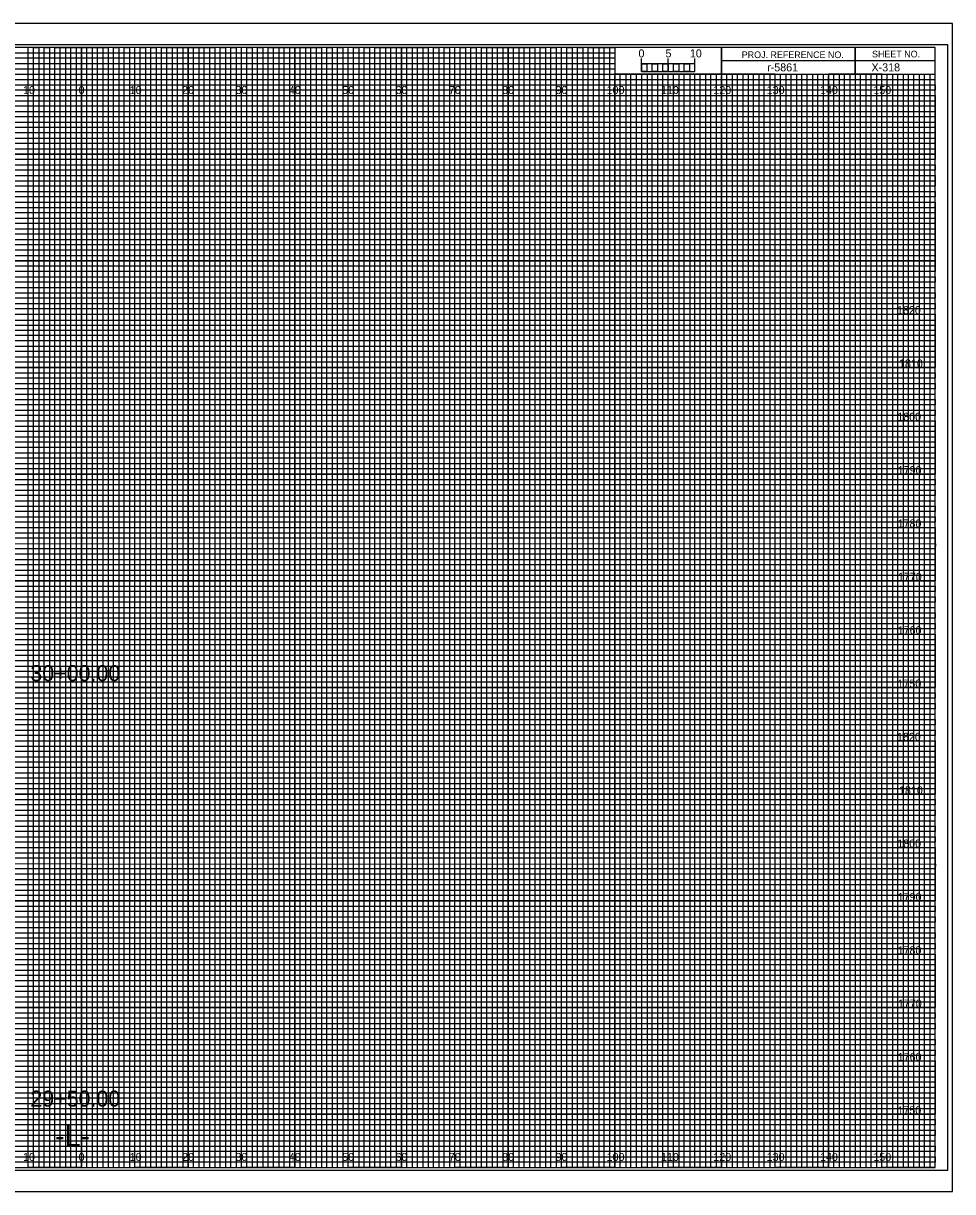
# Model space of a CAD drawing. Extents: x -15 to 323, y -5 to 6170.
# Drawn here: x 149.1 to 323.3, y 3075.5 to 3294.5 of the extents above; entities that cross this region are included whole.
import ezdxf

# ---------------------------------------------------------------- set-up
doc = ezdxf.new("R2010")
doc.units = 0
for name, color, linetype in [('Prop XS Alignment Label', 7, 'Continuous'), ('Prop XS Bar Scale Labels', 7, 'Continuous'), ('Prop XS DDE', 7, 'Continuous'), ('Prop XS DDE Earthwork Shape', 7, 'Continuous'), ('Prop XS DDE Slope Text', 7, 'Continuous'), ('Prop XS DDE Text', 7, 'Continuous'), ('Prop XS Earthwork Shape', 7, 'Continuous'), ('Prop XS Noise Wall', 7, 'Continuous'), ('Prop XS Project Number', 7, 'Continuous'), ('Prop XS Retaining Wall', 7, 'Continuous'), ('Prop XS Station Labels', 7, 'Continuous'), ('Prop XS Temporary Shoring', 7, 'Continuous'), ('Scratch_Level_3', 7, 'Continuous'), ('Scratch_Level_7', 7, 'Continuous'), ('Scratch_Level_8', 7, 'Continuous'), ('Sheet Cross Section Grid Minor 1 CELL', 7, 'Continuous')]:
    doc.layers.add(name, color=color, linetype=linetype)

msp = doc.modelspace()

# ---------------------------------------------------------------- linework, layer by layer
at = {"layer": 'Prop XS Alignment Label'}
for p, q in [((265, 3285.49), (265, 3287.9)), ((265, 3286.9), (265, 3287.9)), ((270, 3285.49), (270, 3287.9)), ((275, 3285.49), (275, 3287.9)), ((275, 3286.9), (275, 3287.9))]:
    msp.add_line(p, q, dxfattribs=at)
for points in [[(275, 3286.9), (265, 3286.9), (265, 3285.49), (275, 3285.49)], [(265, 3286.9), (266, 3286.9), (266, 3285.49), (265, 3285.49)], [(267, 3286.9), (268, 3286.9), (268, 3285.49), (267, 3285.49)], [(269, 3286.9), (270, 3286.9), (270, 3285.49), (269, 3285.49)], [(271, 3286.9), (272, 3286.9), (272, 3285.49), (271, 3285.49)], [(273, 3286.9), (274, 3286.9), (274, 3285.49), (273, 3285.49)]]:
    msp.add_lwpolyline(points, close=True, dxfattribs=at)
at = {"layer": 'Prop XS DDE'}
msp.add_lwpolyline([(-13.4, 3075.5), (323.3, 3075.5), (323.3, 3294.5), (-13.4, 3294.5)], close=True, dxfattribs=at)
at = {"layer": 'Prop XS DDE Slope Text'}
msp.add_lwpolyline([(-10.8, 3079.5), (322.4, 3079.5), (322.4, 3290.5), (-10.8, 3290.5)], close=True, dxfattribs=at)
at = {"layer": 'Prop XS DDE Text'}
for p, q in [((150, 3080), (150, 3290)), ((160, 3080), (160, 3290)), ((170, 3080), (170, 3290)), ((180, 3080), (180, 3290)), ((190, 3080), (190, 3290)), ((200, 3080), (200, 3290)), ((210, 3080), (210, 3290)), ((220, 3080), (220, 3290)), ((230, 3080), (230, 3290)), ((240, 3080), (240, 3290)), ((250, 3080), (250, 3290)), ((260, 3080), (260, 3284.69)), ((270, 3080), (270, 3284.69)), ((280, 3080), (280, 3284.69)), ((290, 3080), (290, 3284.69)), ((300, 3080), (300, 3284.69)), ((310, 3080), (310, 3284.69)), ((0, 3280), (320, 3280)), ((0, 3270), (320, 3270)), ((0, 3260), (320, 3260)), ((0, 3250), (320, 3250)), ((0, 3240), (320, 3240)), ((0, 3230), (320, 3230)), ((0, 3220), (320, 3220)), ((0, 3210), (320, 3210)), ((0, 3200), (320, 3200)), ((0, 3190), (320, 3190)), ((0, 3180), (320, 3180)), ((0, 3170), (320, 3170)), ((0, 3160), (320, 3160)), ((0, 3150), (320, 3150)), ((0, 3140), (320, 3140)), ((0, 3130), (320, 3130)), ((0, 3120), (320, 3120)), ((0, 3110), (320, 3110)), ((0, 3100), (320, 3100)), ((0, 3090), (320, 3090))]:
    msp.add_line(p, q, dxfattribs=at)
at = {"layer": 'Prop XS Earthwork Shape'}
for p, q in [((150, 3290), (140, 3290)), ((150, 3080), (150, 3290)), ((170, 3290), (160, 3290)), ((160, 3290), (160, 3080)), ((170, 3080), (170, 3290)), ((190, 3290), (180, 3290)), ((180, 3290), (180, 3080)), ((190, 3080), (190, 3290)), ((210, 3290), (200, 3290)), ((200, 3290), (200, 3080)), ((210, 3080), (210, 3290)), ((230, 3290), (220, 3290)), ((220, 3290), (220, 3080)), ((230, 3080), (230, 3290)), ((250, 3290), (240, 3290)), ((240, 3290), (240, 3080)), ((250, 3080), (250, 3290)), ((260, 3290), (260, 3080)), ((270, 3080), (270, 3285)), ((290, 3285), (280, 3285)), ((280, 3285), (280, 3080)), ((290, 3080), (290, 3285)), ((310, 3285), (300, 3285)), ((300, 3285), (300, 3080)), ((310, 3080), (310, 3285)), ((160, 3080), (150, 3080)), ((180, 3080), (170, 3080)), ((200, 3080), (190, 3080)), ((220, 3080), (210, 3080)), ((240, 3080), (230, 3080)), ((260, 3080), (250, 3080)), ((280, 3080), (270, 3080)), ((300, 3080), (290, 3080)), ((320, 3080), (310, 3080)), ((320, 3080), (320, 3080))]:
    msp.add_line(p, q, dxfattribs=at)
for points in [[(0, 3280), (320, 3280), (320, 3270), (0, 3270)], [(0, 3260), (320, 3260), (320, 3250), (0, 3250)], [(0, 3240), (320, 3240), (320, 3230), (0, 3230)], [(0, 3220), (320, 3220), (320, 3210), (0, 3210)], [(0, 3200), (320, 3200), (320, 3190), (0, 3190)], [(0, 3180), (320, 3180), (320, 3170), (0, 3170)], [(0, 3160), (320, 3160), (320, 3150), (0, 3150)], [(0, 3140), (320, 3140), (320, 3130), (0, 3130)], [(0, 3120), (320, 3120), (320, 3110), (0, 3110)], [(0, 3100), (320, 3100), (320, 3090), (0, 3090)]]:
    msp.add_lwpolyline(points, dxfattribs=at)
at = {"layer": 'Prop XS Noise Wall'}
for p, q in [((305, 3290), (305, 3285)), ((305, 3285), (305, 3290)), ((280, 3287.5), (280, 3285)), ((320, 3287.49), (280, 3287.49)), ((280, 3285), (320, 3285))]:
    msp.add_line(p, q, dxfattribs=at)
for points in [[(320, 3290), (0, 3290), (0, 3080), (320, 3080)], [(280, 3290), (260, 3290), (260, 3285.03), (280, 3285.03)], [(320, 3290), (280, 3290), (280, 3285), (320, 3285)]]:
    msp.add_lwpolyline(points, close=True, dxfattribs=at)
at = {"layer": 'Prop XS Retaining Wall'}
for p, q in [((267, 3285), (266.01, 3285)), ((266.01, 3285), (266.01, 3080)), ((267, 3080), (267, 3285)), ((269, 3285), (268, 3285)), ((268, 3285), (268, 3080)), ((269, 3080), (269, 3285)), ((266.01, 3080), (265, 3080)), ((268, 3080), (267, 3080))]:
    msp.add_line(p, q, dxfattribs=at)
for points in [[(150, 3080), (151, 3080), (151, 3290), (152, 3290), (152, 3080)], [(152, 3080), (153, 3080), (153, 3290), (154, 3290), (154, 3080)], [(155, 3080), (156, 3080), (156, 3290), (157, 3290), (157, 3080)], [(157, 3080), (158, 3080), (158, 3290), (159, 3290), (159, 3080)], [(160, 3080), (161, 3080), (161, 3290), (162, 3290), (162, 3080)], [(162, 3080), (163, 3080), (163, 3290), (164, 3290), (164, 3080)], [(165, 3080), (166, 3080), (166, 3290), (167, 3290), (167, 3080)], [(167, 3080), (168, 3080), (168, 3290), (169, 3290), (169, 3080)], [(170, 3080), (171, 3080), (171, 3290), (172, 3290), (172, 3080)], [(172, 3080), (173, 3080), (173, 3290), (174, 3290), (174, 3080)], [(175, 3080), (176, 3080), (176, 3290), (177, 3290), (177, 3080)], [(177, 3080), (178, 3080), (178, 3290), (179, 3290), (179, 3080)], [(180, 3080), (181, 3080), (181, 3290), (182, 3290), (182, 3080)], [(182, 3080), (183, 3080), (183, 3290), (184, 3290), (184, 3080)], [(185, 3080), (186, 3080), (186, 3290), (187, 3290), (187, 3080)], [(187, 3080), (188, 3080), (188, 3290), (189, 3290), (189, 3080)], [(190, 3080), (191, 3080), (191, 3290), (192, 3290), (192, 3080)], [(192, 3080), (193, 3080), (193, 3290), (194, 3290), (194, 3080)], [(195, 3080), (196, 3080), (196, 3290), (197, 3290), (197, 3080)], [(197, 3080), (198, 3080), (198, 3290), (199, 3290), (199, 3080)], [(200, 3080), (201, 3080), (201, 3290), (202, 3290), (202, 3080)], [(202, 3080), (203, 3080), (203, 3290), (204, 3290), (204, 3080)], [(205, 3080), (206, 3080), (206, 3290), (207, 3290), (207, 3080)], [(207, 3080), (208, 3080), (208, 3290), (209, 3290), (209, 3080)], [(210, 3080), (211, 3080), (211, 3290), (212, 3290), (212, 3080)], [(212, 3080), (213, 3080), (213, 3290), (214, 3290), (214, 3080)], [(215, 3080), (216, 3080), (216, 3290), (217, 3290), (217, 3080)], [(217, 3080), (218, 3080), (218, 3290), (219, 3290), (219, 3080)], [(220, 3080), (221, 3080), (221, 3290), (222, 3290), (222, 3080)], [(222, 3080), (223, 3080), (223, 3290), (224, 3290), (224, 3080)], [(225, 3080), (226, 3080), (226, 3290), (227, 3290), (227, 3080)], [(227, 3080), (228, 3080), (228, 3290), (229, 3290), (229, 3080)], [(230, 3080), (231, 3080), (231, 3290), (232, 3290), (232, 3080)], [(232, 3080), (233, 3080), (233, 3290), (234, 3290), (234, 3080)], [(235, 3080), (236, 3080), (236, 3290), (237, 3290), (237, 3080)], [(237, 3080), (238, 3080), (238, 3290), (239, 3290), (239, 3080)], [(240, 3080), (241, 3080), (241, 3290), (242, 3290), (242, 3080)], [(242, 3080), (243, 3080), (243, 3290), (244, 3290), (244, 3080)], [(245, 3080), (246, 3080), (246, 3290), (247, 3290), (247, 3080)], [(247, 3080), (248, 3080), (248, 3290), (249, 3290), (249, 3080)], [(250, 3080), (251, 3080), (251, 3290), (252, 3290), (252, 3080)], [(252, 3080), (253, 3080), (253, 3290), (254, 3290), (254, 3080)], [(255, 3080), (256, 3080), (256, 3290), (257, 3290), (257, 3080)], [(257, 3080), (258, 3080), (258, 3290), (259, 3290), (259, 3080)], [(260, 3080), (261, 3080), (261, 3285), (262.02, 3285), (262.02, 3080)], [(262, 3080), (263, 3080), (263, 3285), (263.99, 3285), (263.99, 3080)], [(270, 3080), (270.98, 3080), (270.98, 3285), (272, 3285), (272, 3080)], [(272, 3080), (273, 3080), (273, 3285), (274.05, 3285), (274.05, 3080)], [(275, 3080), (276, 3080), (276, 3285), (277, 3285), (277, 3080)], [(277, 3080), (278, 3080), (278, 3285), (279, 3285), (279, 3080)], [(280, 3080), (281, 3080), (281, 3285), (282, 3285), (282, 3080)], [(282, 3080), (283, 3080), (283, 3285), (284, 3285), (284, 3080)], [(285, 3080), (286, 3080), (286, 3285), (287, 3285), (287, 3080)], [(287, 3080), (288, 3080), (288, 3285), (289, 3285), (289, 3080)], [(290, 3080), (291, 3080), (291, 3285), (292, 3285), (292, 3080)], [(292, 3080), (293, 3080), (293, 3285), (294, 3285), (294, 3080)], [(295, 3080), (296, 3080), (296, 3285), (297, 3285), (297, 3080)], [(297, 3080), (298, 3080), (298, 3285), (299, 3285), (299, 3080)], [(300, 3080), (301, 3080), (301, 3285), (302, 3285), (302, 3080)], [(302, 3080), (303, 3080), (303, 3285), (304, 3285), (304, 3080)], [(305, 3080), (306, 3080), (306, 3285), (307, 3285), (307, 3080)], [(307, 3080), (308, 3080), (308, 3285), (309, 3285), (309, 3080)], [(310, 3080), (311, 3080), (311, 3285), (312, 3285), (312, 3080)], [(312, 3080), (313, 3080), (313, 3285), (314, 3285), (314, 3080)], [(315, 3080), (316, 3080), (316, 3285), (317, 3285), (317, 3080)], [(317, 3080), (318, 3080), (318, 3285), (319, 3285), (319, 3080)]]:
    msp.add_lwpolyline(points, dxfattribs=at)
at = {"layer": 'Prop XS Station Labels'}
for points in [[(145, 3080), (155, 3080), (155, 3290), (165, 3290), (165, 3080), (175, 3080), (175, 3290), (185, 3290), (185, 3080), (195, 3080), (195, 3290), (205, 3290), (205, 3080), (215, 3080), (215, 3290), (225, 3290), (225, 3080), (235, 3080), (235, 3290), (245, 3290), (245, 3080), (255, 3080), (255, 3290), (259.93, 3290), (260, 3290), (260, 3285), (264.99, 3285), (264.99, 3080), (275, 3080), (275, 3285), (285, 3285), (285, 3080), (295, 3080), (295, 3285), (305, 3285), (305, 3080), (315, 3080), (315, 3285)], [(0, 3285), (275, 3285)], [(0, 3265), (320, 3265), (320, 3275), (0, 3275)], [(0, 3245), (320, 3245), (320, 3255), (0, 3255)], [(0, 3225), (320, 3225), (320, 3235), (0, 3235)], [(0, 3205), (320, 3205), (320, 3215), (0, 3215)], [(0, 3185), (320, 3185), (320, 3195), (0, 3195)], [(0, 3165), (320, 3165), (320, 3175), (0, 3175)], [(0, 3145), (320, 3145), (320, 3155), (0, 3155)], [(0, 3125), (320, 3125), (320, 3135), (0, 3135)], [(0, 3105), (320, 3105), (320, 3115), (0, 3115)], [(0, 3085), (320, 3085), (320, 3095), (0, 3095)]]:
    msp.add_lwpolyline(points, dxfattribs=at)
at = {"layer": 'Scratch_Level_7'}
for p, q in [((323.3, 3294.5), (-13.4, 3294.5)), ((-13.4, 3075.5), (323.3, 3075.5))]:
    msp.add_line(p, q, dxfattribs=at)
at = {"layer": 'Sheet Cross Section Grid Minor 1 CELL'}
for p, q in [((0, 3289), (260, 3289)), ((260, 3287.98), (0, 3287.98)), ((260, 3289), (260, 3287.98)), ((0, 3287), (260, 3287)), ((260, 3285.89), (0, 3285.89)), ((260, 3287), (260, 3285.89)), ((0, 3284), (320, 3284))]:
    msp.add_line(p, q, dxfattribs=at)
for points in [[(0, 3283), (270, 3283), (320, 3283), (320, 3282), (0, 3282)], [(0, 3281), (320, 3281), (320, 3279), (0, 3279)], [(0, 3278), (320, 3278), (320, 3277), (0, 3276.98)], [(0, 3276), (320, 3276), (320, 3274), (0, 3274)], [(0, 3273), (320, 3273), (320, 3272), (0, 3272)], [(0, 3271), (320, 3271), (320, 3269), (0, 3269)], [(0, 3268), (320, 3268), (320, 3267), (0, 3267)], [(0, 3266), (320, 3266), (320, 3264), (0, 3264)], [(0, 3263), (320, 3263), (320, 3262), (0, 3262)], [(0, 3261), (320, 3261), (320, 3259), (0, 3259)], [(0, 3258), (320, 3258), (320, 3257), (0, 3257)], [(0, 3256), (320, 3256), (320, 3253.95), (320, 3253), (320, 3252), (0, 3252)], [(0, 3254), (320, 3254), (320, 3253), (0, 3253)], [(0, 3251), (320, 3251), (320, 3249), (0, 3249.03)], [(0, 3249.03), (320, 3249), (320, 3248), (0, 3248)], [(0, 3247), (320, 3247), (320, 3246), (0, 3246)], [(0, 3244), (320, 3244), (320, 3243), (0, 3243)], [(0, 3242), (320, 3242), (320, 3241), (0, 3241)], [(-0.07, 3238.89), (320, 3238.89), (320, 3237.88), (-0.07, 3237.88)], [(0, 3237), (320, 3237), (320, 3236), (0, 3236)], [(0, 3234), (320, 3234), (320, 3233), (0, 3233)], [(0, 3232), (320, 3232), (320, 3231), (0, 3231)], [(0, 3229), (320, 3229), (320, 3228), (0, 3228)], [(0, 3227), (320, 3227), (320, 3226), (0, 3226)], [(0, 3224), (320, 3224), (320, 3223), (0, 3223)], [(0, 3222), (320, 3222), (320, 3221), (0, 3221)], [(0, 3219), (320, 3219), (319.99, 3217.98), (0, 3218)], [(0, 3217), (320, 3217), (320, 3216), (0, 3216)], [(0, 3214), (320, 3214), (320, 3213), (0, 3213)], [(0, 3212), (320, 3212), (320, 3211), (0, 3211)], [(0, 3209), (320, 3209), (320, 3208), (0, 3208)], [(0, 3207), (320, 3207), (320, 3206), (0, 3206)], [(0, 3204), (320, 3204), (320, 3203), (0, 3203)], [(0, 3202), (320, 3202), (320, 3201), (0, 3201)], [(0, 3199), (320, 3199), (320, 3198), (0, 3198)], [(0, 3196.99), (320.07, 3196.91), (320, 3196), (0, 3196)], [(0, 3194), (320, 3194), (320, 3193), (0, 3193)], [(0, 3192), (320, 3192), (320, 3191), (0, 3191)], [(0, 3189), (320, 3189), (320, 3188), (0, 3188)], [(0, 3187), (320, 3187), (320, 3186), (0, 3186)], [(0, 3184), (320, 3184), (320, 3183), (0, 3183)], [(0, 3182), (320, 3182), (320, 3181), (0, 3181)], [(0, 3179), (320, 3179), (320, 3178), (0, 3178)], [(0, 3177), (320, 3177), (320, 3176), (0, 3176)], [(0, 3174), (320, 3174), (320, 3173), (0, 3173)], [(0, 3172), (320, 3172), (320, 3171), (0, 3171)], [(0, 3169), (320, 3169), (320, 3168), (0, 3168)], [(0, 3167), (320, 3167), (320, 3166), (0, 3166)], [(0, 3164), (320, 3164), (320, 3163), (0, 3163)], [(0, 3162), (320, 3162), (320, 3161), (0, 3161)], [(0, 3159), (320, 3159), (319.99, 3157.98), (0, 3158)], [(0, 3157), (320, 3157), (320, 3156), (0, 3156)], [(0, 3154), (320, 3154), (320, 3153), (0, 3153)], [(0, 3152), (320, 3152), (320, 3151), (0, 3151)], [(0, 3149), (320, 3149), (320, 3148), (0, 3148)], [(0, 3147), (320, 3147), (320, 3146), (0, 3146)], [(0, 3144), (320, 3144), (320, 3143), (0, 3143)], [(0, 3142), (320, 3142), (320, 3141), (0, 3141)], [(0, 3139), (320, 3139), (320, 3138), (0, 3138)], [(0, 3136.99), (320.07, 3136.91), (320, 3136), (0, 3136)], [(0, 3134), (320, 3134), (320, 3133), (0, 3133)], [(0, 3132), (320, 3132), (320, 3131), (0, 3131)], [(0, 3129), (320, 3129), (320, 3128), (0, 3128)], [(0, 3127), (320, 3127), (320, 3126), (0, 3126)], [(0, 3124), (320, 3124), (320, 3123), (0, 3123)], [(0, 3122), (320, 3122), (320, 3121), (0, 3121)], [(0, 3119), (320, 3119), (320, 3118), (0, 3118)], [(0, 3117), (320, 3117), (320, 3116), (0, 3116)], [(0, 3114), (320, 3114), (320, 3113), (0, 3113)], [(0, 3112), (320, 3112), (320, 3111), (0, 3111)], [(0, 3109), (320, 3109), (320, 3108), (0, 3108)], [(0, 3107), (320, 3107), (320, 3106), (0, 3106)], [(0, 3104), (320, 3104), (320, 3103), (0, 3103)], [(0, 3102), (320, 3102), (320, 3101), (0, 3101)], [(0, 3099), (320, 3099), (320, 3098), (0, 3098)], [(0, 3097), (320, 3097), (320, 3096), (0, 3096)], [(0, 3094), (320, 3094), (320, 3093), (0, 3093)], [(0, 3092), (320, 3092), (320, 3091), (0, 3091)], [(0, 3089), (320, 3089), (320, 3088), (0, 3088)], [(0, 3087), (320, 3087), (320, 3086), (0, 3086)], [(0, 3084), (320, 3084), (320, 3083), (0, 3083)], [(0, 3082), (320, 3082), (320, 3081), (0, 3081)]]:
    msp.add_lwpolyline(points, dxfattribs=at)

# ---------------------------------------------------------------- texts
at = {"layer": 'Prop XS Alignment Label'}
for s, height, p in [('0', 1.5, (264.41, 3288.12)), ('-L-', 4, (155.06, 3084))]:
    msp.add_text(s, height=height, dxfattribs=at).set_placement(p)
at = {"layer": 'Prop XS Bar Scale Labels'}
for s, p in [('5', (269.47, 3288.12)), ('10', (274.04, 3288.12))]:
    msp.add_text(s, height=1.5, dxfattribs=at).set_placement(p)
at = {"layer": 'Prop XS DDE Earthwork Shape'}
msp.add_text('X-318', height=1.5, dxfattribs=at).set_placement((308.09, 3285.5))
at = {"layer": 'Prop XS Noise Wall'}
for s, p in [('SHEET NO.', (308.19, 3288.12)), ('PROJ. REFERENCE NO.', (283.77, 3287.99))]:
    msp.add_text(s, height=1.25, dxfattribs=at).set_placement(p)
at = {"layer": 'Prop XS Project Number'}
msp.add_text('r-5861', height=1.5, dxfattribs=at).set_placement((288.53, 3285.5))
at = {"layer": 'Prop XS Temporary Shoring'}
for s, p in [('30+00.00', (150.41, 3171.19)), ('29+50.00', (150.41, 3091.44))]:
    msp.add_text(s, height=3, dxfattribs=at).set_placement(p)
at = {"layer": 'Scratch_Level_3'}
for s, p in [('1820', (312.87, 3240)), ('1810', (313.25, 3230)), ('1800', (312.92, 3220)), ('1790', (313, 3210)), ('1780', (312.98, 3200)), ('1770', (313.04, 3190)), ('1760', (313, 3180)), ('1750', (312.96, 3170)), ('1820', (312.87, 3160)), ('1810', (313.25, 3150)), ('1800', (312.92, 3140)), ('1790', (313, 3130)), ('1780', (312.98, 3120)), ('1770', (313.04, 3110)), ('1760', (313, 3100)), ('1750', (312.96, 3090))]:
    msp.add_text(s, height=1.5, dxfattribs=at).set_placement(p)
at = {"layer": 'Scratch_Level_8'}
for s, p in [('10', (149.04, 3281.25)), ('0', (159.45, 3281.25)), ('0', (159.45, 3281.25)), ('10', (169.04, 3281.25)), ('20', (178.86, 3281.25)), ('30', (188.86, 3281.25)), ('40', (198.86, 3281.25)), ('50', (208.86, 3281.25)), ('60', (218.86, 3281.25)), ('70', (228.86, 3281.25)), ('80', (238.86, 3281.25)), ('90', (248.86, 3281.25)), ('100', (258.44, 3281.25)), ('110', (268.62, 3281.25)), ('120', (278.44, 3281.25)), ('130', (288.44, 3281.25)), ('140', (298.44, 3281.25)), ('150', (308.44, 3281.25)), ('10', (149.04, 3081.25)), ('0', (159.45, 3081.25)), ('0', (159.45, 3081.25)), ('10', (169.04, 3081.25)), ('20', (178.86, 3081.25)), ('30', (188.86, 3081.25)), ('40', (198.86, 3081.25)), ('50', (208.86, 3081.25)), ('60', (218.86, 3081.25)), ('70', (228.86, 3081.25)), ('80', (238.86, 3081.25)), ('90', (248.86, 3081.25)), ('100', (258.44, 3081.25)), ('110', (268.62, 3081.25)), ('120', (278.44, 3081.25)), ('130', (288.44, 3081.25)), ('140', (298.44, 3081.25)), ('150', (308.44, 3081.25))]:
    msp.add_text(s, height=1.5, dxfattribs=at).set_placement(p)

doc.saveas('drawing.dxf')
